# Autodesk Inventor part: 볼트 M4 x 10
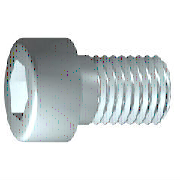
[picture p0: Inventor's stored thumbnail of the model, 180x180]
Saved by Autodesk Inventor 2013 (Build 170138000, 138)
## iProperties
Created: 2012-02
Part Number: 볼트 M4 x 10
Material: 강철, 연강
Description: 원통형 머리 캡 나사
Document SubType Name: Modeling
Standard: JIS B 1176
Designer: mdu-01
Standards Organization: JIS
Language: ko-KR
Size Designation: M4 x 10
Categories: <MemberInstance><Categories><Category DisplayName="조임쇠" InternalName="e4da775c-781d-43d5-af7c-5136215cf5a6" Mnemonic="FSTN"><Category DisplayName="볼트" InternalN
Density: 1 g/cm^3
IsCustomPart: 1
Author: mdu-01
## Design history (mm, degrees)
sketch "스케치1"
  geometry: L1 (-1, 0)-(10, 0); L2 (10, 0)-(10, 2); L3 (10, 2)-(1.75, 2); L4 (1.75, 2)-(1.32, 2); L5 (1.32, 2)-(0, 2); L6 (0, 2)-(0, 3.5); L7 (0, 3.5)-(-4, 3.5); L8 (-4, 3.5)-(-4, 1.732); L9 (-4, 1.732)-(-2, 1.732); L10 (-2, 1.732)-(-1, 0); L11 (-6.8, 0)-(12.8, 0) reference; L12 (0, -0.7)-(0, 4.2) reference; L13 (1.75, 2)-(0, 2)
  constraints: 22 end point, 6 parallel, 2 collinear, 2 perpendicular, 1 horizontal, 1 point on line
  dimensions: "d1" = 8.25 distance from line of L3.end L2 (= GEL); "d2" = 0.42952 distance of L4.end L3.end (computed from GAL); "d3" = 4 distance between parallel lines of L8 L6 (= KOH); "d4" = 2 distance of L8.end L9.end (= INTI); "d5" = 60 deg angle of L10 L1; "d6" = 4 diameter of L3 L1 (= GD); "d7" = 4 diameter of L5 L1 (= BDM); "d8" = 3.4641 diameter of L9 L1 (= 1.1547 x SW); "d9" = 7 diameter of L7 L1 (= KOD); "d26" = 10 distance between parallel lines of L12 L2 (= NLG)
revolve "본체" sketch "스케치1" stored, may be unused: angle "d10" = 90 deg
sketch "스케치2"
  geometry: L1 (0, -4.9)-(0, 4.9) reference; L2 (-4.9, 0)-(4.9, 0) reference; L3 (1.732, 0)-(0.866, -1.5); L4 (0.866, -1.5)-(-0.866, -1.5); L5 (-0.866, -1.5)-(-1.732, 0); L6 (-1.732, 0)-(-0.866, 1.5); L7 (-0.866, 1.5)-(0.866, 1.5); L8 (0.866, 1.5)-(1.732, 0); 2 further points
  constraints: 12 end point, 1 coincident, 1 horizontal alignment, 1 point on line, 12 other
extrude "슬롯" join sketch "스케치2" stored distance "d11" = 10; taper "d12" = 0 deg
workplane "Work Plane1"
fillet "Fillet2" dims "d30" = 0.1 (= R)
body "Solid1"
fillet "모깎기1" dims "d17" = 0.4 (= RR)
feature "스레드" dims "d13" = 8.25 (= GEL), "d14" = 0
chamfer "모따기1" distance "d15" = 0.42941 (= -0.5 x SPD + 0.5 x GD); stored, may be unused: second distance "d16" = 0.42941 (= GUL), angle "d27" = 45 deg
other parameters: "GD" = 4 (= NND) [user parameter; used in 2 equation terms], "NLG" = 10 [user parameter; used in 1 equation term], "GEL" = 8.25 [user parameter; used in 2 equation terms], "KOD" = 7 [user parameter; used in 1 equation term], "KOH" = 4 [user parameter; used in 1 equation term], "INTI" = 2 [user parameter; used in 1 equation term], "GAL" = 0.42941 (= 0.61345 x PTC) [user parameter; used in 1 equation term], "GUL" = 0.42941 (= 0.61345 x PTC) [user parameter; used in 1 equation term], "BDM" = 4 (= NND) [user parameter; used in 1 equation term], "SW" = 3 [user parameter; used in 2 equation terms], "RR" = 0.4 [user parameter; used in 1 equation term], "SPD" = 3.14117 (= NND - 1.2269 x PTC) [user parameter; used in 1 equation term], "d19" = 0, "d28" = 0, "d29" = 0, "R" = 0.1 [user parameter; used in 1 equation term], "PHH" = 0.2 [user parameter], "GD1" = 3.14117 (= THREADDIA - 1.2269 x PTC) [user parameter], "THREADDIA" = 4 [user parameter; used in 1 equation term], "FAWI" = 45 deg [user parameter], "TPU" = 14.28571 (computed from PTC) [user parameter], "PTC" = 0.7 [user parameter; used in 5 equation terms], "NND" = 4 [user parameter; used in 3 equation terms], "TOA" = 30 deg [user parameter], "E0" = 3.465 (= 1.155 x SW) [user parameter]
